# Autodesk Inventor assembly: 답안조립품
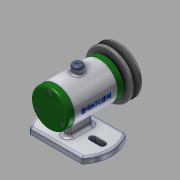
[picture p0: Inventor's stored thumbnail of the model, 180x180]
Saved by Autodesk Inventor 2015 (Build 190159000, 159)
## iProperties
Created: 2017-12
Part Number: 답안조립품
Document SubType Name: Assembly
Designer: SCD-A03
Author: SCD-A03
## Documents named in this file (14)
- D:\471207V1011\답안조립품.iam
- D:\471207V1011\본체.ipt
- D:\471207V1011\V벨트풀리.ipt
- D:\471207V1011\고무캡.ipt
- D:\471207V1011\너트 M 8.ipt
- D:\471207V1011\뒤커버.ipt
- D:\471207V1011\베어링 15 x 32 x 9.ipt
- D:\471207V1011\볼트 M4 x 12.ipt
- D:\471207V1011\스프링와셔 8.ipt
- D:\471207V1011\앞커버.ipt
- D:\471207V1011\오일 실 15 25 7.ipt
- D:\471207V1011\와셔 8x17.ipt
- D:\471207V1011\축.ipt
- D:\471207V1011\키 3 x 3 x 12.ipt
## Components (2 placed, 2 different names)
1. 고무캡:2
2. V벨트풀리:2
